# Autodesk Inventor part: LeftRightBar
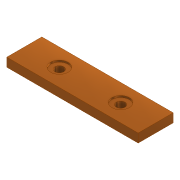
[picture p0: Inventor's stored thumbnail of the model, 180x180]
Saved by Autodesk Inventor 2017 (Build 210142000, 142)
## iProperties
Part Number: LeftRightBar
Material: ゴールド
Document SubType Name: Modeling
Designer: kyushu-hep
Density: 19.3 g/cm^3
Appearance: メタル 1600F 熱
Author: kyushu-hep
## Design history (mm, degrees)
sketch "スケッチ1"
  geometry: L1 (10.301, 13.049)-(-64.699, 13.049); L2 (-64.699, 13.049)-(-64.699, 8.049); L3 (-64.699, 8.049)-(10.301, 8.049); L4 (10.301, 8.049)-(10.301, 13.049); 1 further point
  constraints: 8 end point, 2 parallel, 1 horizontal, 1 perpendicular
  dimensions: "d0" = 75 distance of L3.end L2.end; "d1" = 5 distance of L1.end L2.end
extrude "押し出し1" new body sketch "スケッチ1" distance "d2" = 20; taper "d3" = 0 deg
sketch "スケッチ2"
  geometry: L1 (0, 0)-(0, 20) reference; L2 (75, 0)-(75, 20) reference; L3 (0, 20)-(75, 20) reference; C1 r 5 at (20, 10); C2 r 5 at (55, 10); 1 further point
  constraints: 2 centre point
  dimensions: "d13" = 10 diameter of C1; "d14" = 20 distance from line of L1 C1.centre; "d15" = 10 diameter of C2; "d16" = 20 distance from line of L2 C2.centre; "d25" = 10 distance from line of C1.centre L3; "d26" = 10 distance from line of C2.centre L3
extrude "押し出し2" cut sketch "スケッチ2" distance "d17" = 1; taper "d18" = 0 deg
sketch "スケッチ3"
  geometry: L1 (-20, -10)-(-20, 10) reference; L2 (55, -10)-(55, 10) reference; L3 (-20, 10)-(55, 10) reference; C1 r 2.5 at (0, 0); C2 r 2.5 at (35, 0); 1 further point
  constraints: 2 centre point
  dimensions: "d19" = 5 diameter of C1; "d20" = 5 diameter of C2; "d21" = 20 distance from line of L1 C1.centre; "d22" = 20 distance from line of L2 C2.centre; "d23" = 10 distance from line of L3 C2.centre; "d24" = 10 distance from line of L3 C1.centre
extrude "押し出し3" cut sketch "スケッチ3" distance "d27" = 4; taper "d28" = 0 deg
node "ソリッド1"
